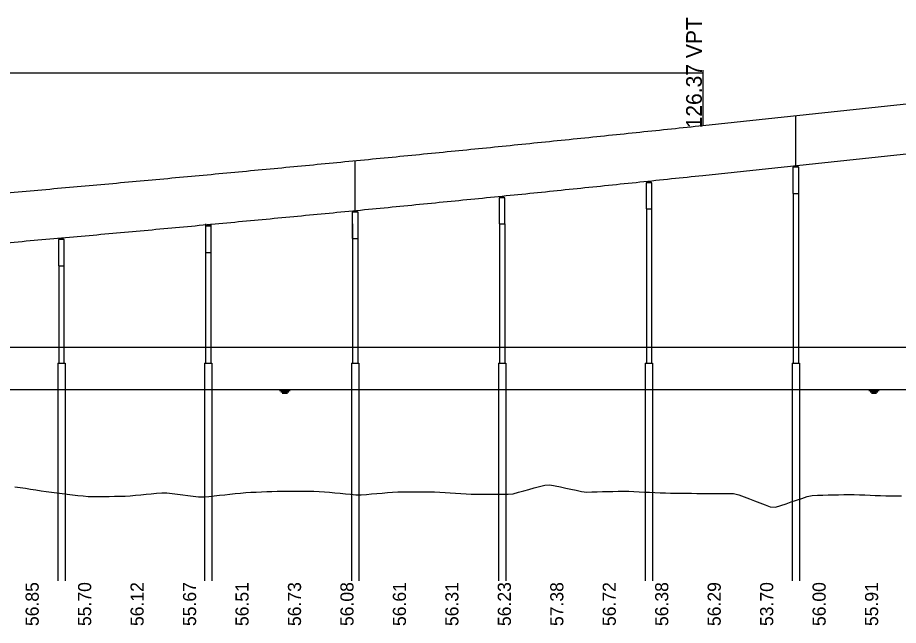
# Model space of a CAD drawing. Extents: x 2121671 to 2169879, y 557274 to 599957.
# Drawn here: x 2153597 to 2154437, y 595763 to 596342 of the extents above; entities that cross this region are included whole.
import ezdxf

# ---------------------------------------------------------------- set-up
doc = ezdxf.new("R2010")
doc.units = 0
for name, color, linetype in [('BR_CONCRETE', 7, 'Continuous'), ('BR_DETAILS', 7, 'Continuous'), ('BR_PRESTRESSED BEAM', 7, 'Continuous'), ('RD_DDB_Profile_Elev', 7, 'Continuous'), ('RD_DDB_Profile_EX', 7, 'Continuous'), ('RD_DDB_Profile_PR', 7, 'Continuous'), ('RD_DDB_StripGrade', 7, 'Continuous'), ('RD_DDB_VCLbl', 7, 'Continuous')]:
    doc.layers.add(name, color=color, linetype=linetype)

msp = doc.modelspace()

# ---------------------------------------------------------------- linework, layer by layer
at = {"layer": 'BR_CONCRETE'}
for p, q in [((2154336.32, 596174.58), (2154336.32, 596013.07)), ((2154336.32, 596174.58), (2154336.32, 596013.07)), ((2154341.32, 596174.58), (2154341.32, 596013.07)), ((2154341.32, 596174.58), (2154341.32, 596013.07)), ((2154196.32, 596159.83), (2154196.32, 596013.07)), ((2154196.32, 596159.83), (2154196.32, 596013.07)), ((2154201.32, 596159.83), (2154201.32, 596013.07)), ((2154201.32, 596159.83), (2154201.32, 596013.07)), ((2153776.32, 596145.51), (2153776.32, 596013.07)), ((2153776.32, 596145.51), (2153776.32, 596013.07)), ((2153781.32, 596145.51), (2153781.32, 596013.07)), ((2153781.32, 596145.51), (2153781.32, 596013.07)), ((2153916.32, 596145.51), (2153916.32, 596013.07)), ((2153916.32, 596145.51), (2153916.32, 596013.07)), ((2153921.32, 596145.51), (2153921.32, 596013.07)), ((2153921.32, 596145.51), (2153921.32, 596013.07)), ((2154056.32, 596145.51), (2154056.32, 596013.07)), ((2154056.32, 596145.51), (2154056.32, 596013.07)), ((2154061.32, 596145.51), (2154061.32, 596013.07)), ((2154061.32, 596145.51), (2154061.32, 596013.07)), ((2153636.32, 596105.75), (2153636.32, 596013.07)), ((2153636.32, 596105.75), (2153636.32, 596013.07)), ((2153641.32, 596105.75), (2153641.32, 596013.07)), ((2153641.32, 596105.75), (2153641.32, 596013.07)), ((2153635.32, 596013.07), (2153635.32, 595805.78)), ((2153635.32, 596013.07), (2153635.32, 595805.78)), ((2153642.32, 596013.07), (2153642.32, 595805.78)), ((2153642.32, 596013.07), (2153642.32, 595805.78)), ((2153775.32, 596013.07), (2153775.32, 595805.78)), ((2153775.32, 596013.07), (2153775.32, 595805.78)), ((2153782.32, 596013.07), (2153782.32, 595805.78)), ((2153782.32, 596013.07), (2153782.32, 595805.78)), ((2153915.32, 596013.07), (2153915.32, 595805.78)), ((2153915.32, 596013.07), (2153915.32, 595805.78)), ((2153922.32, 596013.07), (2153922.32, 595805.78)), ((2153922.32, 596013.07), (2153922.32, 595805.78)), ((2154055.32, 596013.07), (2154055.32, 595805.78)), ((2154055.32, 596013.07), (2154055.32, 595805.78)), ((2154062.32, 596013.07), (2154062.32, 595805.78)), ((2154062.32, 596013.07), (2154062.32, 595805.78)), ((2154195.32, 596013.07), (2154195.32, 595805.78)), ((2154195.32, 596013.07), (2154195.32, 595805.78)), ((2154202.32, 596013.07), (2154202.32, 595805.78)), ((2154202.32, 596013.07), (2154202.32, 595805.78)), ((2154335.32, 596013.07), (2154335.32, 595805.78)), ((2154335.32, 596013.07), (2154335.32, 595805.78)), ((2154342.32, 596013.07), (2154342.32, 595805.78)), ((2154342.32, 596013.07), (2154342.32, 595805.78))]:
    msp.add_line(p, q, dxfattribs=at)
for points in [[(2154336.07, 596174.58), (2154341.57, 596174.58), (2154341.57, 596199.58), (2154336.07, 596199.58)], [(2154336.07, 596174.58), (2154341.57, 596174.58), (2154341.57, 596199.58), (2154336.07, 596199.58)], [(2154196.07, 596159.83), (2154201.57, 596159.83), (2154201.57, 596184.83), (2154196.07, 596184.83)], [(2154196.07, 596159.83), (2154201.57, 596159.83), (2154201.57, 596184.83), (2154196.07, 596184.83)], [(2154056.07, 596145.51), (2154061.57, 596145.51), (2154061.57, 596170.51), (2154056.07, 596170.51)], [(2154056.07, 596145.51), (2154061.57, 596145.51), (2154061.57, 596170.51), (2154056.07, 596170.51)], [(2153916.07, 596131.73), (2153921.57, 596131.73), (2153921.57, 596156.73), (2153916.07, 596156.73)], [(2153916.07, 596131.73), (2153921.57, 596131.73), (2153921.57, 596156.73), (2153916.07, 596156.73)], [(2153776.07, 596118.47), (2153781.57, 596118.47), (2153781.57, 596143.47), (2153776.07, 596143.47)], [(2153776.07, 596118.47), (2153781.57, 596118.47), (2153781.57, 596143.47), (2153776.07, 596143.47)], [(2153636.07, 596105.75), (2153641.57, 596105.75), (2153641.57, 596130.75), (2153636.07, 596130.75)], [(2153636.07, 596105.75), (2153641.57, 596105.75), (2153641.57, 596130.75), (2153636.07, 596130.75)]]:
    msp.add_lwpolyline(points, close=True, dxfattribs=at)
at = {"layer": 'BR_DETAILS'}
for points in [[(2154337.32, 596200.83), (2154338.32, 596200.83), (2154338.32, 596199.58), (2154337.32, 596199.58)], [(2154337.32, 596200.83), (2154338.32, 596200.83), (2154338.32, 596199.58), (2154337.32, 596199.58)], [(2154339.32, 596200.83), (2154340.32, 596200.83), (2154340.32, 596199.58), (2154339.32, 596199.58)], [(2154339.32, 596200.83), (2154340.32, 596200.83), (2154340.32, 596199.58), (2154339.32, 596199.58)], [(2154197.32, 596186.08), (2154198.32, 596186.08), (2154198.32, 596184.83), (2154197.32, 596184.83)], [(2154197.32, 596186.08), (2154198.32, 596186.08), (2154198.32, 596184.83), (2154197.32, 596184.83)], [(2154199.32, 596186.08), (2154200.32, 596186.08), (2154200.32, 596184.83), (2154199.32, 596184.83)], [(2154199.32, 596186.08), (2154200.32, 596186.08), (2154200.32, 596184.83), (2154199.32, 596184.83)], [(2154057.32, 596171.76), (2154058.32, 596171.76), (2154058.32, 596170.51), (2154057.32, 596170.51)], [(2154057.32, 596171.76), (2154058.32, 596171.76), (2154058.32, 596170.51), (2154057.32, 596170.51)], [(2154059.32, 596171.76), (2154060.32, 596171.76), (2154060.32, 596170.51), (2154059.32, 596170.51)], [(2154059.32, 596171.76), (2154060.32, 596171.76), (2154060.32, 596170.51), (2154059.32, 596170.51)], [(2153917.32, 596157.98), (2153918.32, 596157.98), (2153918.32, 596156.73), (2153917.32, 596156.73)], [(2153917.32, 596157.98), (2153918.32, 596157.98), (2153918.32, 596156.73), (2153917.32, 596156.73)], [(2153919.32, 596157.98), (2153920.32, 596157.98), (2153920.32, 596156.73), (2153919.32, 596156.73)], [(2153919.32, 596157.98), (2153920.32, 596157.98), (2153920.32, 596156.73), (2153919.32, 596156.73)], [(2153777.32, 596144.72), (2153778.32, 596144.72), (2153778.32, 596143.47), (2153777.32, 596143.47)], [(2153777.32, 596144.72), (2153778.32, 596144.72), (2153778.32, 596143.47), (2153777.32, 596143.47)], [(2153779.32, 596144.72), (2153780.32, 596144.72), (2153780.32, 596143.47), (2153779.32, 596143.47)], [(2153779.32, 596144.72), (2153780.32, 596144.72), (2153780.32, 596143.47), (2153779.32, 596143.47)], [(2153637.32, 596132), (2153638.32, 596132), (2153638.32, 596130.75), (2153637.32, 596130.75)], [(2153637.32, 596132), (2153638.32, 596132), (2153638.32, 596130.75), (2153637.32, 596130.75)], [(2153639.32, 596132), (2153640.32, 596132), (2153640.32, 596130.75), (2153639.32, 596130.75)], [(2153639.32, 596132), (2153640.32, 596132), (2153640.32, 596130.75), (2153639.32, 596130.75)]]:
    msp.add_lwpolyline(points, close=True, dxfattribs=at)
at = {"layer": 'BR_PRESTRESSED BEAM'}
for p, q in [((2154338.82, 596200.99), (2154338.82, 596248.49)), ((2154338.82, 596200.99), (2154338.82, 596248.49)), ((2154250.24, 596191.8), (2154543.24, 596222.75)), ((2154250.24, 596191.8), (2154543.24, 596222.75)), ((2153918.82, 596158.12), (2153918.82, 596205.62)), ((2153918.82, 596158.12), (2153918.82, 596205.62)), ((2153635.32, 596013.07), (2153642.32, 596013.07)), ((2153635.32, 596013.07), (2153642.32, 596013.07)), ((2153775.32, 596013.07), (2153782.32, 596013.07)), ((2153775.32, 596013.07), (2153782.32, 596013.07)), ((2153915.32, 596013.07), (2153922.32, 596013.07)), ((2153915.32, 596013.07), (2153922.32, 596013.07)), ((2154055.32, 596013.07), (2154062.32, 596013.07)), ((2154055.32, 596013.07), (2154062.32, 596013.07)), ((2154195.32, 596013.07), (2154202.32, 596013.07)), ((2154195.32, 596013.07), (2154202.32, 596013.07)), ((2154335.32, 596013.07), (2154342.32, 596013.07)), ((2154335.32, 596013.07), (2154342.32, 596013.07))]:
    msp.add_line(p, q, dxfattribs=at)
msp.add_spline([(2152750.24, 596063.82), (2152780.24, 596065.79), (2152810.24, 596067.77), (2152840.24, 596069.78), (2152870.24, 596071.82), (2152900.24, 596073.88), (2152930.24, 596075.96), (2152960.24, 596078.07), (2152990.24, 596080.2), (2153020.24, 596082.36), (2153050.24, 596084.54), (2153080.24, 596086.75), (2153110.24, 596088.98), (2153140.24, 596091.23), (2153170.24, 596093.51), (2153200.24, 596095.82), (2153230.24, 596098.14), (2153260.24, 596100.5), (2153290.24, 596102.87), (2153320.24, 596105.27), (2153350.24, 596107.7), (2153380.24, 596110.15), (2153410.24, 596112.62), (2153440.24, 596115.12), (2153470.24, 596117.65), (2153500.24, 596120.19), (2153530.24, 596122.76), (2153560.24, 596125.36), (2153590.24, 596127.98), (2153620.24, 596130.63), (2153650.24, 596133.29), (2153680.24, 596135.99), (2153710.24, 596138.71), (2153740.24, 596141.45), (2153770.24, 596144.22), (2153800.24, 596147.01), (2153830.24, 596149.82), (2153860.24, 596152.66), (2153890.24, 596155.53), (2153920.24, 596158.41), (2153950.24, 596161.33), (2153980.24, 596164.26), (2154010.24, 596167.23), (2154040.24, 596170.21), (2154070.24, 596173.22), (2154100.24, 596176.26), (2154130.24, 596179.32), (2154160.24, 596182.4), (2154190.24, 596185.51), (2154220.24, 596188.64), (2154250.24, 596191.8)], degree=3, dxfattribs=at)
msp.add_spline([(2152750.24, 596063.82), (2152780.24, 596065.79), (2152810.24, 596067.77), (2152840.24, 596069.78), (2152870.24, 596071.82), (2152900.24, 596073.88), (2152930.24, 596075.96), (2152960.24, 596078.07), (2152990.24, 596080.2), (2153020.24, 596082.36), (2153050.24, 596084.54), (2153080.24, 596086.75), (2153110.24, 596088.98), (2153140.24, 596091.23), (2153170.24, 596093.51), (2153200.24, 596095.82), (2153230.24, 596098.14), (2153260.24, 596100.5), (2153290.24, 596102.87), (2153320.24, 596105.27), (2153350.24, 596107.7), (2153380.24, 596110.15), (2153410.24, 596112.62), (2153440.24, 596115.12), (2153470.24, 596117.65), (2153500.24, 596120.19), (2153530.24, 596122.76), (2153560.24, 596125.36), (2153590.24, 596127.98), (2153620.24, 596130.63), (2153650.24, 596133.29), (2153680.24, 596135.99), (2153710.24, 596138.71), (2153740.24, 596141.45), (2153770.24, 596144.22), (2153800.24, 596147.01), (2153830.24, 596149.82), (2153860.24, 596152.66), (2153890.24, 596155.53), (2153920.24, 596158.41), (2153950.24, 596161.33), (2153980.24, 596164.26), (2154010.24, 596167.23), (2154040.24, 596170.21), (2154070.24, 596173.22), (2154100.24, 596176.26), (2154130.24, 596179.32), (2154160.24, 596182.4), (2154190.24, 596185.51), (2154220.24, 596188.64), (2154250.24, 596191.8)], degree=3, dxfattribs=at)
at = {"layer": 'RD_DDB_Profile_Elev'}
for p, q in [((2151940.69, 596028.07), (2155629.71, 596028.07)), ((2151971.97, 595988.07), (2156334.94, 595988.07)), ((2153846.76, 595986.82), (2153856.76, 595986.82)), ((2153848.01, 595985.57), (2153855.51, 595985.57)), ((2153849.26, 595984.32), (2153854.26, 595984.32)), ((2154408.32, 595986.82), (2154418.32, 595986.82)), ((2154409.57, 595985.57), (2154417.07, 595985.57)), ((2154410.82, 595984.32), (2154415.82, 595984.32))]:
    msp.add_line(p, q, dxfattribs=at)
at = {"layer": 'RD_DDB_Profile_EX'}
for points in [[(2153594.48, 595895.41), (2153599.48, 595894.64), (2153604.48, 595893.86), (2153609.48, 595893.09), (2153614.48, 595892.32), (2153619.48, 595891.54), (2153624.48, 595890.77), (2153629.48, 595890.17), (2153634.48, 595889.59), (2153639.48, 595888.98), (2153644.48, 595888.37), (2153649.48, 595887.76), (2153654.48, 595887.15), (2153659.48, 595886.54), (2153664.48, 595885.94), (2153669.48, 595886), (2153674.48, 595886.07), (2153679.48, 595886.14), (2153684.48, 595886.21), (2153689.48, 595886.28), (2153694.48, 595886.35)], [(2153694.48, 595886.35), (2153699.48, 595886.42), (2153704.48, 595886.75), (2153709.48, 595887.24), (2153714.48, 595887.72), (2153719.48, 595888.21), (2153724.48, 595888.7), (2153729.48, 595889.19), (2153734.48, 595889.68), (2153739.48, 595889.43), (2153744.48, 595888.78), (2153749.48, 595888.15), (2153754.48, 595887.53), (2153759.48, 595886.9), (2153764.48, 595886.28), (2153769.48, 595885.65), (2153774.48, 595885.64), (2153779.48, 595886.17), (2153784.48, 595886.7), (2153789.48, 595887.24), (2153794.48, 595887.77), (2153799.48, 595888.3), (2153804.48, 595888.83), (2153809.48, 595889.37), (2153814.48, 595889.89), (2153819.48, 595890.09), (2153824.48, 595890.28), (2153829.48, 595890.47), (2153834.48, 595890.66), (2153839.48, 595890.85), (2153844.48, 595891.04), (2153849.48, 595891.23), (2153854.48, 595891.27), (2153859.48, 595891.22), (2153864.48, 595891.16), (2153869.48, 595891.11), (2153874.48, 595891.06), (2153879.48, 595891), (2153884.48, 595890.95), (2153889.48, 595890.65), (2153894.48, 595890.17), (2153899.48, 595889.69), (2153904.48, 595889.2), (2153909.48, 595888.72), (2153914.48, 595888.24), (2153919.48, 595887.76), (2153924.48, 595887.59), (2153929.48, 595888.02), (2153934.48, 595888.45), (2153939.48, 595888.87), (2153944.48, 595889.3), (2153949.48, 595889.72), (2153954.48, 595890.15), (2153959.48, 595890.49), (2153964.48, 595890.5), (2153969.48, 595890.51), (2153974.48, 595890.52), (2153979.48, 595890.53), (2153984.48, 595890.54), (2153989.48, 595890.56), (2153994.48, 595890.57), (2153999.48, 595890.24), (2154004.48, 595889.91), (2154009.48, 595889.58), (2154014.48, 595889.25), (2154019.48, 595888.92), (2154024.48, 595888.6), (2154029.48, 595888.27), (2154034.48, 595888.28), (2154039.48, 595888.26), (2154044.48, 595888.25), (2154049.48, 595888.23), (2154054.48, 595888.21), (2154059.48, 595888.19), (2154064.48, 595888.18), (2154069.48, 595888.74), (2154074.48, 595890.11), (2154079.48, 595891.49), (2154084.48, 595892.86), (2154089.48, 595894.24), (2154094.48, 595895.61), (2154099.48, 595896.99), (2154104.48, 595897.3), (2154109.48, 595896.23), (2154114.48, 595895.17), (2154119.48, 595894.11), (2154124.48, 595893.05), (2154129.48, 595891.99), (2154134.48, 595890.93), (2154139.48, 595890.22), (2154144.48, 595890.37), (2154149.48, 595890.51), (2154154.48, 595890.66), (2154159.48, 595890.81), (2154164.48, 595890.95), (2154169.48, 595891.1), (2154174.48, 595891.28), (2154179.48, 595891.04), (2154184.48, 595890.8), (2154189.48, 595890.55), (2154194.48, 595890.3)], [(2154194.48, 595890.3), (2154199.48, 595890.05), (2154204.48, 595889.8), (2154209.48, 595889.55), (2154214.48, 595889.41), (2154219.48, 595889.35), (2154224.48, 595889.29), (2154229.48, 595889.24), (2154234.48, 595889.18), (2154239.48, 595889.12), (2154244.48, 595889.06), (2154249.48, 595889.05), (2154254.48, 595889.01), (2154259.48, 595888.97), (2154264.48, 595888.93), (2154269.48, 595888.89), (2154274.48, 595888.85), (2154279.48, 595888.81), (2154284.48, 595887.76), (2154289.48, 595885.85), (2154294.48, 595883.93), (2154299.48, 595882.01), (2154304.48, 595880.1), (2154309.48, 595878.18), (2154314.48, 595876.26), (2154319.48, 595875.84), (2154324.48, 595877.53), (2154329.48, 595879.22), (2154334.48, 595880.91), (2154339.48, 595882.6), (2154344.48, 595884.29), (2154349.48, 595885.97), (2154354.48, 595887.08), (2154359.48, 595887.22), (2154364.48, 595887.36), (2154369.48, 595887.5), (2154374.48, 595887.64), (2154379.48, 595887.78), (2154384.48, 595887.93), (2154389.48, 595887.99), (2154394.48, 595887.82), (2154399.48, 595887.65), (2154404.48, 595887.49), (2154409.48, 595887.32), (2154414.48, 595887.15), (2154419.48, 595886.99), (2154424.48, 595886.83), (2154429.48, 595886.76), (2154434.48, 595886.69), (2154439.48, 595886.62)]]:
    msp.add_lwpolyline(points, dxfattribs=at)
at = {"layer": 'RD_DDB_Profile_PR'}
msp.add_line((2154250.24, 596239.3), (2154693.24, 596286.09), dxfattribs=at)
msp.add_spline([(2152750.24, 596111.33), (2152780.24, 596113.29), (2152810.24, 596115.28), (2152840.24, 596117.29), (2152870.24, 596119.32), (2152900.24, 596121.38), (2152930.24, 596123.47), (2152960.24, 596125.57), (2152990.24, 596127.71), (2153020.24, 596129.86), (2153050.24, 596132.05), (2153080.24, 596134.25), (2153110.24, 596136.48), (2153140.24, 596138.74), (2153170.24, 596141.02), (2153200.24, 596143.32), (2153230.24, 596145.65), (2153260.24, 596148), (2153290.24, 596150.38), (2153320.24, 596152.78), (2153350.24, 596155.2), (2153380.24, 596157.65), (2153410.24, 596160.13), (2153440.24, 596162.62), (2153470.24, 596165.15), (2153500.24, 596167.69), (2153530.24, 596170.27), (2153560.24, 596172.86), (2153590.24, 596175.48), (2153620.24, 596178.13), (2153650.24, 596180.8), (2153680.24, 596183.49), (2153710.24, 596186.21), (2153740.24, 596188.95), (2153770.24, 596191.72), (2153800.24, 596194.51), (2153830.24, 596197.32), (2153860.24, 596200.16), (2153890.24, 596203.03), (2153920.24, 596205.91), (2153950.24, 596208.83), (2153980.24, 596211.76), (2154010.24, 596214.73), (2154040.24, 596217.71), (2154070.24, 596220.72), (2154100.24, 596223.76), (2154130.24, 596226.82), (2154160.24, 596229.9), (2154190.24, 596233.01), (2154220.24, 596236.14), (2154250.24, 596239.3)], degree=3, dxfattribs=at)
at = {"layer": 'RD_DDB_VCLbl'}
for p, q in [((2154250.24, 596291.8), (2154250.24, 596239.3)), ((2152750.24, 596289.3), (2154250.24, 596289.3))]:
    msp.add_line(p, q, dxfattribs=at)

# ---------------------------------------------------------------- texts
at = {"layer": 'RD_DDB_StripGrade'}
for s, height, p in [('126.37 VPT', 15, (2154249.24, 596236.47)), ('56.85', 12.5, (2153617.24, 595762.7)), ('55.70', 12.5, (2153667.24, 595762.7)), ('56.12', 12.5, (2153717.24, 595762.7)), ('55.67', 12.5, (2153767.24, 595762.7)), ('56.51', 12.5, (2153817.24, 595762.7)), ('56.73', 12.5, (2153867.24, 595762.7)), ('56.08', 12.5, (2153917.24, 595762.7)), ('56.61', 12.5, (2153967.24, 595762.7)), ('56.31', 12.5, (2154017.24, 595762.7)), ('56.23', 12.5, (2154067.24, 595762.7)), ('57.38', 12.5, (2154117.24, 595762.7)), ('56.72', 12.5, (2154167.24, 595762.7)), ('56.38', 12.5, (2154217.24, 595762.7)), ('56.29', 12.5, (2154267.24, 595762.7)), ('53.70', 12.5, (2154317.24, 595762.7)), ('56.00', 12.5, (2154367.24, 595762.7)), ('55.91', 12.5, (2154417.24, 595762.7))]:
    msp.add_text(s, height=height, rotation=90, dxfattribs=at).set_placement(p)

doc.saveas('drawing.dxf')
